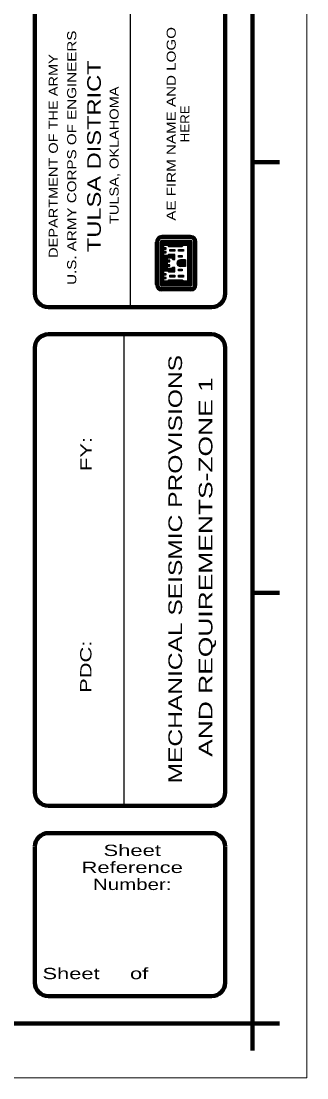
# Model space of a CAD drawing. Extents: x 55 to 190, y 198 to 264.
# Drawn here: x 140.29 to 146.59, y 198.45 to 221.76 of the extents above; entities that cross this region are included whole.
import ezdxf
from ezdxf.enums import TextEntityAlignment as Align

# ---------------------------------------------------------------- set-up
doc = ezdxf.new("R2010")
doc.units = 0
doc.header["$LTSCALE"] = 0.1
for name, color, linetype, lineweight in [('1', 7, 'Continuous', 25), ('3', 7, 'Continuous', 25), ('6', 7, 'Continuous', 25)]:
    doc.layers.add(name, color=color, linetype=linetype, lineweight=lineweight)

msp = doc.modelspace()

# ---------------------------------------------------------------- linework, layer by layer
at = {"layer": '1'}
for p, q in [((142.6927, 231.855), (142.6927, 215.4537)), ((142.559, 204.4512), (142.559, 214.8537))]:
    msp.add_line(p, q, dxfattribs=at)
at = {"layer": '1', "lineweight": 80}
for p, q in [((140.5927, 231.555), (140.5927, 215.7537)), ((144.7927, 215.7537), (144.7927, 231.555)), ((145.9927, 218.6512), (145.3927, 218.6512)), ((140.8927, 215.4537), (144.4927, 215.4537)), ((144.4927, 214.8537), (140.8927, 214.8537)), ((140.5927, 214.5537), (140.5927, 204.7512)), ((144.7927, 204.7512), (144.7927, 214.5537)), ((145.9927, 209.1512), (145.3927, 209.1512)), ((140.8927, 204.4512), (144.4927, 204.4512)), ((140.8927, 203.8512), (144.4927, 203.8512)), ((140.5927, 200.5512), (140.5927, 203.5512)), ((144.7927, 203.5512), (144.7927, 200.5512)), ((144.4927, 200.2512), (140.8927, 200.2512)), ((145.3927, 199.6512), (145.3927, 199.0512)), ((145.9927, 199.6512), (145.3927, 199.6512))]:
    msp.add_line(p, q, dxfattribs=at)
at = {"layer": '1', "lineweight": 13}
msp.add_lwpolyline([(62.4915, 257.8525), (146.5927, 257.8525), (146.5927, 198.4512), (62.4915, 198.4512)], close=True, dxfattribs=at)
at = {"layer": '1', "lineweight": 80}
msp.add_lwpolyline([(65.1915, 256.6525), (145.3927, 256.6525), (145.3927, 199.6512), (65.1915, 199.6512)], close=True, dxfattribs=at)
for centre, start, end in [((140.8922, 215.7538), 180, 270), ((144.4922, 215.7538), 270, 0), ((140.8922, 214.5538), 90, 180), ((144.4922, 214.5538), 0, 90), ((140.8922, 204.7517), 180, 270), ((144.4922, 204.7517), 270, 0), ((140.8925, 203.5517), 90, 180), ((144.4925, 203.5517), 0, 90), ((140.8925, 200.5517), 180, 270), ((144.4925, 200.5517), 270, 0)]:
    msp.add_arc(centre, 0.3, start, end, dxfattribs=at)
at = {"layer": '6'}
for p, q in [((144.0552, 217.0287), (143.3652, 217.0287)), ((144.0277, 217.0325), (143.394, 217.0325)), ((143.2565, 215.9525), (143.2565, 216.89)), ((143.3252, 216.9212), (143.2577, 216.9212)), ((143.3202, 216.9037), (143.2577, 216.9037)), ((143.3202, 216.8862), (143.2577, 216.8862)), ((143.3202, 216.8687), (143.2577, 216.8687)), ((143.3202, 216.85), (143.2577, 216.85)), ((143.3202, 216.8337), (143.2577, 216.8337)), ((143.3202, 216.815), (143.2577, 216.815)), ((143.3202, 216.7975), (143.2577, 216.7975)), ((143.3377, 216.94), (143.264, 216.94)), ((143.3565, 216.9562), (143.2715, 216.9562)), ((144.139, 216.975), (143.2827, 216.975)), ((144.1227, 216.9937), (143.3015, 216.9937)), ((144.1002, 217.0112), (143.3202, 217.0112)), ((143.3202, 215.9475), (143.3202, 216.895)), ((143.3602, 215.9525), (143.3602, 216.89)), ((144.0627, 216.8862), (143.3602, 216.8862)), ((144.0627, 216.8687), (143.3602, 216.8687)), ((144.0627, 216.85), (143.3602, 216.85)), ((144.0627, 216.8337), (143.3602, 216.8337)), ((143.4377, 216.815), (143.3602, 216.815)), ((143.4377, 216.7975), (143.3602, 216.7975)), ((144.0602, 216.9037), (143.3627, 216.9037)), ((144.0452, 216.9212), (143.3777, 216.9212)), ((144.0315, 216.965), (143.3915, 216.965)), ((144.0277, 216.925), (143.394, 216.925)), ((143.8627, 216.815), (143.5202, 216.815)), ((143.8465, 216.7975), (143.5377, 216.7975)), ((144.0627, 216.815), (143.9577, 216.815)), ((144.0627, 216.7975), (143.9577, 216.7975)), ((144.0627, 215.9475), (144.0627, 216.8862)), ((144.1502, 216.9562), (144.0652, 216.9562)), ((144.159, 216.94), (144.0852, 216.94)), ((144.164, 216.9212), (144.0965, 216.9212)), ((144.1652, 216.9037), (144.1002, 216.9037)), ((144.1002, 215.9475), (144.1002, 216.895)), ((144.1652, 216.8862), (144.1002, 216.8862)), ((144.1652, 216.8687), (144.1002, 216.8687)), ((144.1652, 216.85), (144.1002, 216.85)), ((144.1652, 216.8337), (144.1002, 216.8337)), ((144.1652, 216.815), (144.1002, 216.815)), ((144.1652, 216.7975), (144.1002, 216.7975)), ((144.1665, 215.9525), (144.1665, 216.89)), ((143.3202, 216.78), (143.2577, 216.78)), ((143.3202, 216.7625), (143.2577, 216.7625)), ((143.3202, 216.7437), (143.2577, 216.7437)), ((143.3202, 216.7275), (143.2577, 216.7275)), ((143.3202, 216.7087), (143.2577, 216.7087)), ((143.3202, 216.6912), (143.2577, 216.6912)), ((143.3202, 216.6737), (143.2577, 216.6737)), ((143.3202, 216.6562), (143.2577, 216.6562)), ((143.3202, 216.6375), (143.2577, 216.6375)), ((143.3202, 216.6212), (143.2577, 216.6212)), ((143.3202, 216.6025), (143.2577, 216.6025)), ((143.3202, 216.585), (143.2577, 216.585)), ((143.3202, 216.5675), (143.2577, 216.5675)), ((143.4377, 216.78), (143.3602, 216.78)), ((143.4377, 216.7625), (143.3602, 216.7625)), ((143.4902, 216.7437), (143.3602, 216.7437)), ((143.4377, 216.7275), (143.3602, 216.7275)), ((143.4377, 216.71), (143.3602, 216.71)), ((143.4377, 216.6912), (143.3602, 216.6912)), ((143.4902, 216.6737), (143.3602, 216.6737)), ((143.4902, 216.6562), (143.3602, 216.6562)), ((143.4377, 216.6375), (143.3602, 216.6375)), ((143.4377, 216.6212), (143.3602, 216.6212)), ((143.4377, 216.6025), (143.3602, 216.6025)), ((143.6802, 216.585), (143.3602, 216.585)), ((143.6802, 216.5675), (143.3602, 216.5675)), ((143.4377, 216.68), (143.4377, 216.7337)), ((143.6802, 216.6037), (143.5315, 216.6037)), ((143.6802, 216.7087), (143.569, 216.7087)), ((143.6802, 216.6912), (143.569, 216.6912)), ((143.869, 216.7087), (143.764, 216.7087)), ((143.869, 216.6912), (143.764, 216.6912)), ((143.8427, 216.585), (143.764, 216.585)), ((143.8427, 216.5675), (143.764, 216.5675)), ((144.0627, 216.78), (143.9577, 216.78)), ((144.0627, 216.7625), (143.9577, 216.7625)), ((144.0627, 216.7437), (143.9577, 216.7437)), ((144.0627, 216.7275), (143.9577, 216.7275)), ((144.0627, 216.7087), (143.9577, 216.7087)), ((144.0627, 216.6912), (143.9577, 216.6912)), ((144.0627, 216.6737), (143.9577, 216.6737)), ((144.0627, 216.6562), (143.9577, 216.6562)), ((144.0627, 216.6375), (143.9577, 216.6375)), ((144.0627, 216.6212), (143.9577, 216.6212)), ((144.0627, 216.6025), (143.9577, 216.6025)), ((144.0627, 216.585), (143.9577, 216.585)), ((144.0627, 216.5675), (143.9577, 216.5675)), ((144.1652, 216.78), (144.1002, 216.78)), ((144.1652, 216.7625), (144.1002, 216.7625)), ((144.1652, 216.7437), (144.1002, 216.7437)), ((144.1652, 216.7275), (144.1002, 216.7275)), ((144.1652, 216.7087), (144.1002, 216.7087)), ((144.1652, 216.6912), (144.1002, 216.6912)), ((144.1652, 216.6737), (144.1002, 216.6737)), ((144.1652, 216.6562), (144.1002, 216.6562)), ((144.1652, 216.6375), (144.1002, 216.6375)), ((144.1652, 216.6212), (144.1002, 216.6212)), ((144.1652, 216.6025), (144.1002, 216.6025)), ((144.1652, 216.585), (144.1002, 216.585)), ((144.1652, 216.5675), (144.1002, 216.5675)), ((143.3202, 216.55), (143.2577, 216.55)), ((143.3202, 216.5312), (143.2577, 216.5312)), ((143.3202, 216.515), (143.2577, 216.515)), ((143.3202, 216.4962), (143.2577, 216.4962)), ((143.3202, 216.4787), (143.2577, 216.4787)), ((143.3202, 216.4612), (143.2577, 216.4612)), ((143.3202, 216.4437), (143.2577, 216.4437)), ((143.3202, 216.425), (143.2577, 216.425)), ((143.3202, 216.4087), (143.2577, 216.4087)), ((143.3202, 216.39), (143.2577, 216.39)), ((143.3202, 216.3725), (143.2577, 216.3725)), ((143.3202, 216.355), (143.2577, 216.355)), ((143.3202, 216.3375), (143.2577, 216.3375)), ((143.6802, 216.55), (143.3602, 216.55)), ((143.5152, 216.5312), (143.3602, 216.5312)), ((143.5152, 216.515), (143.3602, 216.515)), ((143.5152, 216.515), (143.3602, 216.515)), ((143.5152, 216.4962), (143.3602, 216.4962)), ((143.569, 216.4787), (143.3602, 216.4787)), ((143.569, 216.4612), (143.3602, 216.4612)), ((143.5152, 216.4437), (143.3602, 216.4437)), ((143.5152, 216.425), (143.3602, 216.425)), ((143.5152, 216.4087), (143.3602, 216.4087)), ((143.5152, 216.39), (143.3602, 216.39)), ((143.569, 216.3725), (143.3602, 216.3725)), ((143.5152, 216.355), (143.3602, 216.355)), ((143.5152, 216.3375), (143.3602, 216.3375)), ((143.6802, 216.5325), (143.614, 216.5325)), ((143.6802, 216.515), (143.6277, 216.515)), ((143.9127, 216.425), (143.724, 216.425)), ((143.9127, 216.4087), (143.7265, 216.4087)), ((143.9127, 216.4437), (143.7302, 216.4437)), ((143.9127, 216.39), (143.7352, 216.39)), ((143.9127, 216.4612), (143.7402, 216.4612)), ((143.9127, 216.3725), (143.749, 216.3725)), ((143.9127, 216.4787), (143.7565, 216.4787)), ((143.9127, 216.355), (143.7752, 216.355)), ((143.9127, 216.4962), (143.8027, 216.4962)), ((143.9127, 216.3487), (143.9127, 216.495)), ((144.0627, 216.55), (143.9577, 216.55)), ((144.0627, 216.5312), (143.9577, 216.5312)), ((144.0627, 216.515), (143.9577, 216.515)), ((144.0627, 216.4962), (143.9577, 216.4962)), ((144.0627, 216.4787), (143.9577, 216.4787)), ((144.0627, 216.4612), (143.9577, 216.4612)), ((144.0627, 216.4437), (143.9577, 216.4437)), ((144.0627, 216.425), (143.9577, 216.425)), ((144.0627, 216.4087), (143.9577, 216.4087)), ((144.0627, 216.39), (143.9577, 216.39)), ((144.0627, 216.3725), (143.9577, 216.3725)), ((144.0627, 216.355), (143.9577, 216.355)), ((144.0627, 216.3375), (143.9577, 216.3375)), ((144.1652, 216.55), (144.1002, 216.55)), ((144.1652, 216.5312), (144.1002, 216.5312)), ((144.1652, 216.515), (144.1002, 216.515)), ((144.1652, 216.4962), (144.1002, 216.4962)), ((144.1652, 216.4787), (144.1002, 216.4787)), ((144.1652, 216.4612), (144.1002, 216.4612)), ((144.1652, 216.4437), (144.1002, 216.4437)), ((144.1652, 216.425), (144.1002, 216.425)), ((144.1652, 216.4087), (144.1002, 216.4087)), ((144.1652, 216.39), (144.1002, 216.39)), ((144.1652, 216.3725), (144.1002, 216.3725)), ((144.1652, 216.355), (144.1002, 216.355)), ((144.1652, 216.3375), (144.1002, 216.3375)), ((143.3202, 216.3187), (143.2577, 216.3187)), ((143.3202, 216.3025), (143.2577, 216.3025)), ((143.3202, 216.2837), (143.2577, 216.2837)), ((143.3202, 216.2662), (143.2577, 216.2662)), ((143.3202, 216.2475), (143.2577, 216.2475)), ((143.3202, 216.2312), (143.2577, 216.2312)), ((143.3202, 216.2125), (143.2577, 216.2125)), ((143.3202, 216.195), (143.2577, 216.195)), ((143.3202, 216.1775), (143.2577, 216.1775)), ((143.3202, 216.16), (143.2577, 216.16)), ((143.3202, 216.1412), (143.2577, 216.1412)), ((143.3202, 216.125), (143.2577, 216.125)), ((143.3202, 216.1062), (143.2577, 216.1062)), ((143.5152, 216.3187), (143.3602, 216.3187)), ((143.5152, 216.3025), (143.3602, 216.3025)), ((143.6802, 216.2837), (143.3602, 216.2837)), ((143.6802, 216.2662), (143.3602, 216.2662)), ((143.4377, 216.2475), (143.3602, 216.2475)), ((143.4377, 216.2312), (143.3602, 216.2312)), ((143.4377, 216.2125), (143.3602, 216.2125)), ((143.4377, 216.195), (143.3602, 216.195)), ((143.489, 216.1775), (143.3602, 216.1775)), ((143.4377, 216.16), (143.3602, 216.16)), ((143.4377, 216.1412), (143.3602, 216.1412)), ((143.4377, 216.125), (143.3602, 216.125)), ((143.4902, 216.1062), (143.3602, 216.1062)), ((143.6802, 216.25), (143.5202, 216.25)), ((143.6802, 216.2312), (143.5377, 216.2312)), ((143.6802, 216.1412), (143.569, 216.1412)), ((143.6802, 216.125), (143.569, 216.125)), ((143.6802, 216.3025), (143.6077, 216.3025)), ((143.6802, 216.3187), (143.624, 216.3187)), ((143.8427, 216.2837), (143.764, 216.2837)), ((143.8427, 216.2662), (143.764, 216.2662)), ((143.869, 216.1412), (143.764, 216.1412)), ((143.869, 216.125), (143.764, 216.125)), ((144.0627, 216.3187), (143.9577, 216.3187)), ((144.0627, 216.3025), (143.9577, 216.3025)), ((144.0627, 216.2837), (143.9577, 216.2837)), ((144.0627, 216.2662), (143.9577, 216.2662)), ((144.0627, 216.2475), (143.9577, 216.2475)), ((144.0627, 216.2312), (143.9577, 216.2312)), ((144.0627, 216.2125), (143.9577, 216.2125)), ((144.0627, 216.195), (143.9577, 216.195)), ((144.0627, 216.1775), (143.9577, 216.1775)), ((144.0627, 216.16), (143.9577, 216.16)), ((144.0627, 216.1412), (143.9577, 216.1412)), ((144.0627, 216.125), (143.9577, 216.125)), ((144.0627, 216.1062), (143.9577, 216.1062)), ((144.1652, 216.3187), (144.1002, 216.3187)), ((144.1652, 216.3025), (144.1002, 216.3025)), ((144.1652, 216.2837), (144.1002, 216.2837)), ((144.1652, 216.2662), (144.1002, 216.2662)), ((144.1652, 216.2475), (144.1002, 216.2475)), ((144.1652, 216.2312), (144.1002, 216.2312)), ((144.1652, 216.2125), (144.1002, 216.2125)), ((144.1652, 216.195), (144.1002, 216.195)), ((144.1652, 216.1775), (144.1002, 216.1775)), ((144.1652, 216.16), (144.1002, 216.16)), ((144.1652, 216.1412), (144.1002, 216.1412)), ((144.1652, 216.125), (144.1002, 216.125)), ((144.1652, 216.1062), (144.1002, 216.1062)), ((143.3202, 216.09), (143.2577, 216.09)), ((143.3202, 216.0712), (143.2577, 216.0712)), ((143.3202, 216.0537), (143.2577, 216.0537)), ((143.3202, 216.035), (143.2577, 216.035)), ((143.3202, 216.0187), (143.2577, 216.0187)), ((143.3202, 216), (143.2577, 216)), ((143.3202, 215.9825), (143.2577, 215.9825)), ((143.3202, 215.965), (143.2577, 215.965)), ((143.3202, 215.9475), (143.2577, 215.9475)), ((143.3252, 215.9287), (143.2577, 215.9287)), ((143.3302, 215.9125), (143.2602, 215.9125)), ((143.3452, 215.8937), (143.2677, 215.8937)), ((143.3915, 215.8762), (143.2765, 215.8762)), ((143.4902, 216.09), (143.3602, 216.09)), ((143.4377, 216.0712), (143.3602, 216.0712)), ((143.4377, 216.0537), (143.3602, 216.0537)), ((143.4377, 216.035), (143.3602, 216.035)), ((144.0627, 216.0187), (143.3602, 216.0187)), ((144.0627, 216), (143.3602, 216)), ((144.0627, 215.9825), (143.3602, 215.9825)), ((144.0627, 215.965), (143.3602, 215.965)), ((144.0627, 215.9475), (143.3602, 215.9475)), ((144.054, 215.9287), (143.3677, 215.9287)), ((144.0315, 215.8762), (143.3915, 215.8762)), ((144.0277, 215.9162), (143.394, 215.9162)), ((143.8577, 216.0375), (143.5277, 216.0375)), ((144.0627, 216.09), (143.9577, 216.09)), ((144.0627, 216.0712), (143.9577, 216.0712)), ((144.0627, 216.0537), (143.9577, 216.0537)), ((144.0627, 216.035), (143.9577, 216.035)), ((144.1452, 215.8762), (144.0315, 215.8762)), ((144.154, 215.8937), (144.0765, 215.8937)), ((144.1615, 215.9125), (144.0915, 215.9125)), ((144.1652, 215.9287), (144.099, 215.9287)), ((144.1652, 216.09), (144.1002, 216.09)), ((144.1652, 216.0712), (144.1002, 216.0712)), ((144.1652, 216.0537), (144.1002, 216.0537)), ((144.1652, 216.035), (144.1002, 216.035)), ((144.1652, 216.0187), (144.1002, 216.0187)), ((144.1652, 216), (144.1002, 216)), ((144.1652, 215.9825), (144.1002, 215.9825)), ((144.1652, 215.965), (144.1002, 215.965)), ((144.1652, 215.9475), (144.1002, 215.9475)), ((144.1327, 215.8587), (143.2902, 215.8587)), ((144.1152, 215.8412), (143.3065, 215.8412)), ((144.0852, 215.8225), (143.3377, 215.8225)), ((144.0277, 215.81), (143.394, 215.81))]:
    msp.add_line(p, q, dxfattribs=at)
for points in [[(143.4377, 216.7337), (143.4902, 216.7337), (143.4902, 216.76), (143.4377, 216.76), (143.4377, 216.8212), (143.5152, 216.8212), (143.5402, 216.7937), (143.8427, 216.7937), (143.869, 216.8212), (143.9577, 216.8212), (143.9577, 216.0225)], [(143.4902, 216.6537), (143.4902, 216.68), (143.4377, 216.68)], [(143.9577, 216.0225), (143.8727, 216.0225), (143.8427, 216.05), (143.5402, 216.05), (143.5152, 216.0225), (143.4377, 216.0225), (143.4377, 216.0825), (143.4902, 216.0825), (143.4902, 216.1087), (143.4377, 216.1087), (143.4377, 216.1625), (143.4902, 216.1625), (143.4902, 216.1887), (143.4377, 216.1887), (143.4377, 216.255), (143.5152, 216.255), (143.5402, 216.2287), (143.6802, 216.2287), (143.6802, 216.3287), (143.6327, 216.3287), (143.6077, 216.3025), (143.5152, 216.3025), (143.5152, 216.355), (143.569, 216.355), (143.569, 216.3887), (143.5152, 216.3887), (143.5152, 216.455), (143.569, 216.455), (143.569, 216.4875), (143.5152, 216.4875), (143.5152, 216.5412), (143.6077, 216.5412), (143.6327, 216.5075), (143.6802, 216.5075), (143.6802, 216.6137), (143.5402, 216.6137), (143.5152, 216.5887), (143.4377, 216.5887), (143.4377, 216.6537), (143.4902, 216.6537)], [(143.9577, 216.0225), (143.8727, 216.0225), (143.8427, 216.05), (143.5402, 216.05), (143.5152, 216.0225), (143.4377, 216.0225), (143.4377, 216.0825), (143.4902, 216.0825), (143.4902, 216.1087), (143.4377, 216.1087), (143.4377, 216.1625), (143.4902, 216.1625), (143.4902, 216.1887), (143.4377, 216.1887), (143.4377, 216.255), (143.5152, 216.255), (143.5402, 216.2287), (143.6802, 216.2287), (143.6802, 216.3287)], [(143.9127, 216.4962), (143.9127, 216.3487), (143.8027, 216.3487)]]:
    msp.add_lwpolyline(points, dxfattribs=at)
for points in [[(143.6802, 216.6875), (143.569, 216.6875), (143.569, 216.7275), (143.6802, 216.7275)], [(143.869, 216.6875), (143.764, 216.6875), (143.764, 216.7275), (143.869, 216.7275)], [(143.8427, 216.5537), (143.764, 216.5537), (143.764, 216.5887), (143.8427, 216.5887)], [(143.6802, 216.1162), (143.569, 216.1162), (143.569, 216.1562), (143.6802, 216.1562)], [(143.8427, 216.255), (143.764, 216.255), (143.764, 216.2887), (143.8427, 216.2887)], [(143.869, 216.1162), (143.764, 216.1162), (143.764, 216.1562), (143.869, 216.1562)]]:
    msp.add_lwpolyline(points, close=True, dxfattribs=at)
for centre, major_axis, start_param, end_param in [((143.3943, 216.8908), (0, -0.1417), 3.1415927, 4.712389), ((144.0277, 216.8908), (0, 0.1417), 4.712389, 6.2831853), ((143.3901, 216.8951), (0, -0.0709), 3.1415927, 4.712389), ((143.3943, 216.8908), (0, -0.0354), 3.1415927, 4.712389), ((144.0277, 216.8908), (0, 0.0354), 4.712389, 6.2831853), ((144.0319, 216.8951), (0, 0.0709), 4.712389, 6.2831853), ((143.8068, 216.4116), (0, -0.0858), 3.191454, 4.577619), ((143.8068, 216.4346), (0, -0.0858), 4.8471589, 6.2333239), ((143.3943, 215.9525), (0, -0.1417), 4.712389, 6.2831853), ((143.3901, 215.9483), (0, -0.0709), 4.712389, 6.2831853), ((143.3943, 215.9525), (0, -0.0354), 4.712389, 6.2831853), ((144.0277, 215.9525), (0, -0.1417), 6.2831853, 7.8539816), ((144.0277, 215.9525), (0, 0.0354), 3.1415927, 4.712389), ((144.0319, 215.9483), (0, 0.0709), 3.1415927, 4.712389)]:
    msp.add_ellipse(centre, major_axis=major_axis, ratio=0.9801, start_param=start_param, end_param=end_param, dxfattribs=at)

# ---------------------------------------------------------------- texts
at = {"layer": '1'}
for s, height, width, p in [('U.S. ARMY CORPS OF ENGINEERS', 0.2, 1.25, (141.5052, 218.7488)), ('AE FIRM NAME AND LOGO', 0.2, 1.25, (143.7002, 219.4963)), ('DEPARTMENT OF THE ARMY', 0.2, 1.2, (141.099, 218.7863)), ('TULSA DISTRICT', 0.3, 1.3, (142.0477, 218.7825)), ('TULSA, OKLAHOMA', 0.2, 1.2, (142.4402, 218.8038)), ('HERE', 0.2, 1.1, (144.0002, 219.4962)), ('FY:   ', 0.2488, 1.45, (141.844, 212.4144)), ('PDC:                ', 0.2488, 1.45, (141.8402, 208.5925))]:
    msp.add_text(s, height=height, rotation=90, dxfattribs=dict(at, width=width)).set_placement(p, align=Align.CENTER)
for s, width, p in [('Sheet', 1.45, (142.7402, 203.345)), ('Reference', 1.45, (142.7402, 202.97)), ('Number:', 1.35, (142.7402, 202.595))]:
    msp.add_text(s, height=0.25, dxfattribs=dict(at, width=width)).set_placement(p, align=Align.CENTER)
at = {"layer": '3'}
for s, width, p in [('  MECHANICAL SEISMIC PROVISIONS  ', 1.35, (143.839, 209.6725)), ('     AND REQUIREMENTS-ZONE 1     ', 1.45, (144.509, 209.7187))]:
    msp.add_text(s, height=0.3, rotation=90, dxfattribs=dict(at, width=width)).set_placement(p, align=Align.CENTER)
at = {"layer": '3', "width": 1.45}
msp.add_text('Sheet     of', height=0.2488, dxfattribs=at).set_placement((140.7602, 200.6287))
msp.add_text('Sheet     of', height=0.2488, dxfattribs=at).set_placement((140.7602, 200.6287))

doc.saveas('drawing.dxf')
